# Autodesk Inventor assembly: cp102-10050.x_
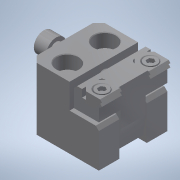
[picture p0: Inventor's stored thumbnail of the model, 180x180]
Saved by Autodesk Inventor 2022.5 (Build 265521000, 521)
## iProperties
Part Number: cp102-10050.x_
Material: 一般
Document SubType Name: Assembly
Designer: ImaoCorp
Sending System: SOLIDWORKS 2017-2017317
MC: AMD64
MC_MODEL: Intel64 Family 6 Model 60 Stepping 3, GenuineIntel
OS: Windows_NT
FRU: Parasolid Version 29.0, build 201,  4-17-2017
FORMAT: text
GUISE: transmit
KEY: cp102-10050
FILE: cp102-10050.x_t
DATE: Thu Apr 04 16:34:48 2019
Author: ImaoCorp
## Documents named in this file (3)
- X:\14_SW2022-Inv2022\00_全2023-1023新製品(TCC)まで\c\cp102-10050\CP102-10050.iam
- X:\14_SW2022-Inv2022\00_全2023-1023新製品(TCC)まで\c\cp102-10050\cp102-10050_01.ipt
- X:\14_SW2022-Inv2022\00_全2023-1023新製品(TCC)まで\c\cp102-10050\cp102-10050_02.ipt
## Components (2 placed, 2 different names)
1. cp102-10050_01
2. cp102-10050_02
